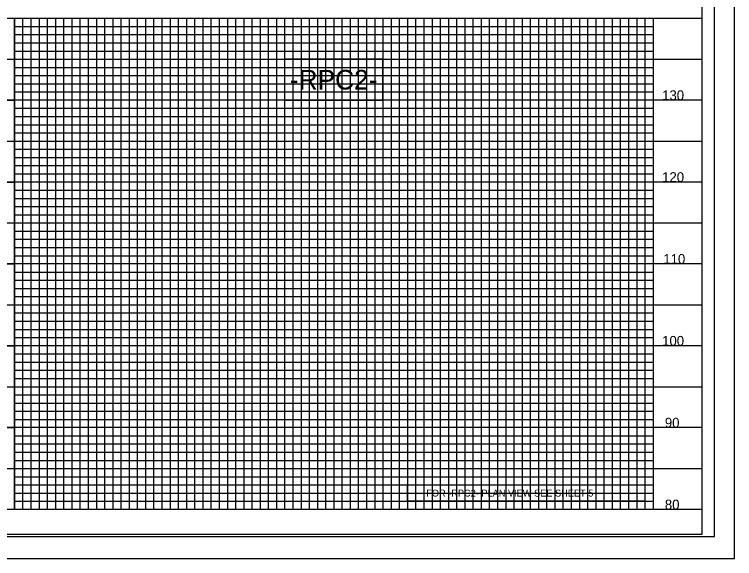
# Model space of a CAD drawing. Extents: x 270 to 1290, y -4845 to -4185.
# Drawn here: x 850 to 1289.8, y -4844.8 to -4512.4 of the extents above; entities that cross this region are included whole.
import ezdxf

# ---------------------------------------------------------------- set-up
doc = ezdxf.new("R2010")
doc.units = 0
for name, color, linetype in [('Exist Vertical Profile Vertical Axis Label', 7, 'Continuous'), ('Prop Grid Mask', 7, 'Continuous'), ('Prop PFL Text', 7, 'Continuous'), ('Scratch_Level_1', 7, 'Continuous'), ('Sheet Cutting Line CELL', 7, 'Continuous'), ('Sheet Layout Profile Border Port 2', 7, 'Continuous'), ('Sheet Plot Border Inside CELL', 7, 'Continuous'), ('Sheet Plot Border Outside CELL', 7, 'Continuous'), ('Sheet Profile CELL', 7, 'Continuous'), ('Sheet Profile Grid Major CELL', 7, 'Continuous'), ('Sheet Profile Grid Middle CELL', 7, 'Continuous'), ('Sheet Profile Grid Minor CELL', 7, 'Continuous')]:
    doc.layers.add(name, color=color, linetype=linetype)

msp = doc.modelspace()

# ---------------------------------------------------------------- linework, layer by layer
at = {"layer": 'Exist Vertical Profile Vertical Axis Label'}
msp.add_lwpolyline([(1090, -4799.75), (1235, -4799.75), (1235, -4809.75), (1090, -4809.75)], close=True, dxfattribs=at)
at = {"layer": 'Prop Grid Mask'}
for points in [[(1015, -4564.75), (1075, -4564.75), (1075, -4539.75), (1015, -4539.75)], [(1090, -4799.75), (1235, -4799.75), (1235, -4809.75), (1090, -4809.75)]]:
    msp.add_lwpolyline(points, close=True, dxfattribs=at)
at = {"layer": 'Prop PFL Text'}
msp.add_lwpolyline([(1015, -4564.75), (1075, -4564.75), (1075, -4539.75), (1015, -4539.75)], close=True, dxfattribs=at)
at = {"layer": 'Scratch_Level_1'}
msp.add_lwpolyline([(850, -4514.75), (1240, -4514.75), (1240, -4814.75), (850, -4814.75)], close=True, dxfattribs=at)
at = {"layer": 'Sheet Cutting Line CELL'}
for p, q in [((1289.8, -4844.75), (1289.8, -4184.75)), ((269.8, -4844.75), (1289.8, -4844.75))]:
    msp.add_line(p, q, dxfattribs=at)
at = {"layer": 'Sheet Layout Profile Border Port 2'}
msp.add_lwpolyline([(400, -4514.75), (1240, -4514.75), (1240, -4814.75), (400, -4814.75)], close=True, dxfattribs=at)
at = {"layer": 'Sheet Plot Border Inside CELL'}
msp.add_lwpolyline([(277.6, -4831.28), (1277.5, -4831.28), (1277.5, -4198.22), (277.6, -4198.22)], close=True, dxfattribs=at)
at = {"layer": 'Sheet Plot Border Outside CELL'}
msp.add_lwpolyline([(269.8, -4844.75), (1289.8, -4844.75), (1289.8, -4184.75), (269.8, -4184.75)], close=True, dxfattribs=at)
at = {"layer": 'Sheet Profile CELL'}
for p, q in [((370, -4514.75), (1270, -4514.75)), ((1270, -4814.75), (370, -4814.75)), ((370, -4829.75), (1270, -4829.75))]:
    msp.add_line(p, q, dxfattribs=at)
msp.add_lwpolyline([(1270, -4199.75), (370, -4199.75), (370, -4829.75), (1270, -4829.75)], close=True, dxfattribs=at)
at = {"layer": 'Sheet Profile Grid Major CELL'}
for p, q in [((850, -4514.75), (850, -4814.75)), ((875, -4514.75), (875, -4814.75)), ((900, -4514.75), (900, -4814.75)), ((925, -4514.75), (925, -4814.75)), ((950, -4514.75), (950, -4814.75)), ((975, -4514.75), (975, -4814.75)), ((1000, -4514.75), (1000, -4814.75)), ((1025, -4514.75), (1025, -4814.75)), ((1050, -4514.75), (1050, -4814.75)), ((1075, -4514.75), (1075, -4814.75)), ((1100, -4514.75), (1100, -4814.75)), ((1125, -4514.75), (1125, -4814.75)), ((1150, -4514.75), (1150, -4814.75)), ((1175, -4514.75), (1175, -4814.75)), ((1200, -4514.75), (1200, -4814.75)), ((1225, -4514.75), (1225, -4814.75)), ((1240, -4514.75), (1240, -4814.75)), ((370, -4539.75), (1270, -4539.75)), ((800, -4539.75), (850, -4539.75)), ((1270, -4564.75), (370, -4564.75)), ((800, -4564.75), (850, -4564.75)), ((370, -4589.75), (1270, -4589.75)), ((800, -4589.75), (850, -4589.75)), ((1270, -4614.75), (370, -4614.75)), ((800, -4614.75), (850, -4614.75)), ((370, -4639.75), (1270, -4639.75)), ((800, -4639.75), (850, -4639.75)), ((1270, -4664.75), (370, -4664.75)), ((800, -4664.75), (850, -4664.75)), ((370, -4689.75), (1270, -4689.75)), ((800, -4689.75), (850, -4689.75)), ((1270, -4714.75), (370, -4714.75)), ((800, -4714.75), (850, -4714.75)), ((370, -4739.75), (1270, -4739.75)), ((800, -4739.75), (850, -4739.75)), ((1270, -4764.75), (370, -4764.75)), ((800, -4764.75), (850, -4764.75)), ((370, -4789.75), (1270, -4789.75))]:
    msp.add_line(p, q, dxfattribs=at)
at = {"layer": 'Sheet Profile Grid Middle CELL'}
for p, q in [((850, -4519.75), (1240, -4519.75)), ((850, -4524.75), (1240, -4524.75)), ((850, -4529.75), (1240, -4529.75)), ((850, -4534.75), (1240, -4534.75)), ((850, -4544.75), (1240, -4544.75)), ((850, -4549.75), (1240, -4549.75)), ((850, -4554.75), (1240, -4554.75)), ((850, -4559.75), (1240, -4559.75)), ((850, -4569.75), (1240, -4569.75)), ((850, -4574.75), (1240, -4574.75)), ((850, -4579.75), (1240, -4579.75)), ((850, -4584.75), (1240, -4584.75)), ((850, -4594.75), (1240, -4594.75)), ((850, -4599.75), (1240, -4599.75)), ((850, -4604.75), (1240, -4604.75)), ((850, -4609.75), (1240, -4609.75)), ((850, -4619.75), (1240, -4619.75)), ((850, -4624.75), (1240, -4624.75)), ((850, -4629.75), (1240, -4629.75)), ((850, -4634.75), (1240, -4634.75)), ((850, -4644.75), (1240, -4644.75)), ((850, -4649.75), (1240, -4649.75)), ((850, -4654.75), (1240, -4654.75)), ((850, -4659.75), (1240, -4659.75)), ((850, -4669.75), (1240, -4669.75)), ((850, -4674.75), (1240, -4674.75)), ((850, -4679.75), (1240, -4679.75)), ((850, -4684.75), (1240, -4684.75)), ((850, -4694.75), (1240, -4694.75)), ((850, -4699.75), (1240, -4699.75)), ((850, -4704.75), (1240, -4704.75)), ((850, -4709.75), (1240, -4709.75)), ((850, -4719.75), (1240, -4719.75)), ((850, -4724.75), (1240, -4724.75)), ((850, -4729.75), (1240, -4729.75)), ((850, -4734.75), (1240, -4734.75)), ((850, -4744.75), (1240, -4744.75)), ((850, -4749.75), (1240, -4749.75)), ((850, -4754.75), (1240, -4754.75)), ((850, -4759.75), (1240, -4759.75)), ((850, -4769.75), (1240, -4769.75)), ((850, -4774.75), (1240, -4774.75)), ((850, -4779.75), (1240, -4779.75)), ((850, -4784.75), (1240, -4784.75)), ((850, -4794.75), (1240, -4794.75)), ((850, -4799.75), (1240, -4799.75)), ((850, -4804.75), (1240, -4804.75)), ((850, -4809.75), (1240, -4809.75))]:
    msp.add_line(p, q, dxfattribs=at)
msp.add_lwpolyline([(1165, -4649.75), (1240, -4649.75)], dxfattribs=at)
at = {"layer": 'Sheet Profile Grid Minor CELL'}
for p, q in [((855, -4514.75), (855, -4814.75)), ((860, -4514.75), (860, -4814.75)), ((865, -4514.75), (865, -4814.75)), ((870, -4514.75), (870, -4814.75)), ((880, -4514.75), (880, -4814.75)), ((885, -4514.75), (885, -4814.75)), ((890, -4514.75), (890, -4814.75)), ((895, -4514.75), (895, -4814.75)), ((905, -4514.75), (905, -4814.75)), ((910, -4514.75), (910, -4814.75)), ((915, -4514.75), (915, -4814.75)), ((920, -4514.75), (920, -4814.75)), ((930, -4514.75), (930, -4814.75)), ((935, -4514.75), (935, -4814.75)), ((940, -4514.75), (940, -4814.75)), ((945, -4514.75), (945, -4814.75)), ((955, -4514.75), (955, -4814.75)), ((960, -4514.75), (960, -4814.75)), ((965, -4514.75), (965, -4814.75)), ((970, -4514.75), (970, -4814.75)), ((980, -4514.75), (980, -4814.75)), ((985, -4514.75), (985, -4814.75)), ((990, -4514.75), (990, -4814.75)), ((995, -4514.75), (995, -4814.75)), ((1005, -4514.75), (1005, -4814.75)), ((1010, -4514.75), (1010, -4814.75)), ((1015, -4514.75), (1015, -4814.75)), ((1020, -4514.75), (1020, -4814.75)), ((1030, -4514.75), (1030, -4814.75)), ((1035, -4514.75), (1035, -4814.75)), ((1040, -4514.75), (1040, -4814.75)), ((1045, -4514.75), (1045, -4814.75)), ((1055, -4514.75), (1055, -4814.75)), ((1060, -4514.75), (1060, -4814.75)), ((1065, -4514.75), (1065, -4814.75)), ((1070, -4514.75), (1070, -4814.75)), ((1080, -4514.75), (1080, -4814.75)), ((1085, -4514.75), (1085, -4814.75)), ((1090, -4514.75), (1090, -4814.75)), ((1095, -4514.75), (1095, -4814.75)), ((1105, -4514.75), (1105, -4814.75)), ((1110, -4514.75), (1110, -4814.75)), ((1115, -4514.75), (1115, -4814.75)), ((1120, -4514.75), (1120, -4814.75)), ((1130, -4514.75), (1130, -4814.75)), ((1135, -4514.75), (1135, -4814.75)), ((1140, -4514.75), (1140, -4814.75)), ((1145, -4514.75), (1145, -4814.75)), ((1155, -4514.75), (1155, -4814.75)), ((1160, -4514.75), (1160, -4814.75)), ((1165, -4514.75), (1165, -4814.75)), ((1170, -4514.75), (1170, -4814.75)), ((1180, -4514.75), (1180, -4814.75)), ((1185, -4514.75), (1185, -4814.75)), ((1190, -4514.75), (1190, -4814.75)), ((1195, -4514.75), (1195, -4814.75)), ((1205, -4514.75), (1205, -4814.75)), ((1210, -4514.75), (1210, -4814.75)), ((1215, -4514.75), (1215, -4814.75)), ((1220, -4514.75), (1220, -4814.75)), ((1230, -4514.75), (1230, -4814.75)), ((1235, -4514.75), (1235, -4814.75))]:
    msp.add_line(p, q, dxfattribs=at)

# ---------------------------------------------------------------- texts
at = {"layer": 'Exist Vertical Profile Vertical Axis Label'}
for s, p in [('130', (1245.56, -4564.75)), ('120', (1245.56, -4614.75)), ('110', (1246.28, -4664.75)), ('100', (1245.56, -4714.75)), ('90', (1247.21, -4764.75)), ('80', (1247.21, -4814.75))]:
    msp.add_text(s, height=6, dxfattribs=at).set_placement(p)
at = {"layer": 'Prop PFL Text'}
for s, height, p in [('-RPC2-', 12, (1018.18, -4558.25)), ('FOR -RPC2- PLAN VIEW SEE SHEET 5', 4.2, (1101.47, -4806.85))]:
    msp.add_text(s, height=height, dxfattribs=at).set_placement(p)

doc.saveas('drawing.dxf')
